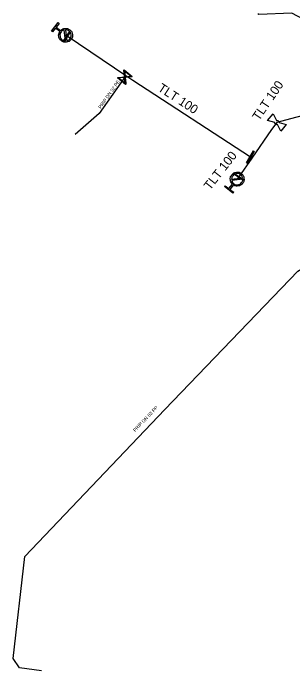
# Model space of a CAD drawing. Extents: x -643544 to -637295, y -1119190 to -1111715.
# Drawn here: x -642499.1 to -642458.3, y -1113951.4 to -1113855.6 of the extents above; entities that cross this region are included whole.
import ezdxf

# ---------------------------------------------------------------- set-up
doc = ezdxf.new("R2010")
doc.units = 0
for name, color, linetype in [('Default', 7, 'Continuous'), ('VP Hydrant', 7, 'Continuous'), ('VP Lomový bod', 7, 'Continuous'), ('VP Popis přípojky', 7, 'Continuous'), ('VP Přípojka', 7, 'Continuous'), ('VP Řad', 7, 'Continuous'), ('VP Řad - popis', 7, 'Continuous'), ('VP Šoupě', 7, 'Continuous')]:
    doc.layers.add(name, color=color, linetype=linetype)

msp = doc.modelspace()

# ---------------------------------------------------------------- linework, layer by layer
at = {"layer": 'Default'}
for points in [[(-642492.138, -1113858.184), (-642491.894, -1113857.919), (-642491.53, -1113857.876), (-642491.12, -1113857.827), (-642490.793, -1113858.083), (-642490.466, -1113858.338), (-642490.417, -1113858.749), (-642490.367, -1113859.16), (-642490.623, -1113859.487), (-642490.877, -1113859.812), (-642491.288, -1113859.863), (-642491.698, -1113859.914), (-642492.024, -1113859.659), (-642492.352, -1113859.403), (-642492.404, -1113858.993), (-642492.451, -1113858.629), (-642492.251, -1113858.329)], [(-642491.599, -1113858.078), (-642491.872, -1113858.139), (-642492.053, -1113858.37), (-642492.261, -1113858.636), (-642492.22, -1113858.969), (-642492.179, -1113859.302), (-642491.913, -1113859.51), (-642491.682, -1113859.691), (-642491.402, -1113859.684)], [(-642491.221, -1113859.662), (-642490.951, -1113859.598), (-642490.773, -1113859.371), (-642490.566, -1113859.106), (-642490.606, -1113858.772), (-642490.646, -1113858.438), (-642490.912, -1113858.23), (-642491.14, -1113858.052), (-642491.418, -1113858.056)], [(-642460.545, -1113871.868), (-642460.597, -1113871.877), (-642460.65, -1113871.868), (-642460.733, -1113871.854), (-642460.797, -1113871.803), (-642460.86, -1113871.751), (-642460.892, -1113871.67), (-642460.912, -1113871.621), (-642460.913, -1113871.568)], [(-642460.656, -1113871.251), (-642460.604, -1113871.242), (-642460.551, -1113871.25), (-642460.467, -1113871.266), (-642460.403, -1113871.317), (-642460.34, -1113871.369), (-642460.309, -1113871.447), (-642460.289, -1113871.498), (-642460.288, -1113871.551)], [(-642467.086, -1113880.528), (-642467.351, -1113880.284), (-642467.394, -1113879.92), (-642467.443, -1113879.51), (-642467.186, -1113879.183), (-642466.931, -1113878.856), (-642466.521, -1113878.807), (-642466.11, -1113878.757), (-642465.782, -1113879.013), (-642465.458, -1113879.267), (-642465.407, -1113879.678), (-642465.356, -1113880.088), (-642465.611, -1113880.414), (-642465.867, -1113880.742), (-642466.277, -1113880.794), (-642466.641, -1113880.841), (-642466.941, -1113880.641)], [(-642465.608, -1113879.611), (-642465.671, -1113879.341), (-642465.899, -1113879.163), (-642466.164, -1113878.956), (-642466.498, -1113878.996), (-642466.832, -1113879.036), (-642467.04, -1113879.302), (-642467.218, -1113879.53), (-642467.214, -1113879.808)], [(-642467.192, -1113879.989), (-642467.131, -1113880.262), (-642466.9, -1113880.443), (-642466.634, -1113880.651), (-642466.301, -1113880.61), (-642465.967, -1113880.569), (-642465.759, -1113880.303), (-642465.579, -1113880.072), (-642465.585, -1113879.792)]]:
    msp.add_open_spline(points, degree=3, dxfattribs=at)
at = {"layer": 'VP Hydrant'}
for points in [[(-642492.251, -1113858.329), (-642492.898, -1113857.824), (-642493.322, -1113858.367), (-642493.467, -1113858.254), (-642492.504, -1113857.023), (-642492.36, -1113857.136), (-642492.784, -1113857.679), (-642492.138, -1113858.184)], [(-642491.402, -1113859.684), (-642491.599, -1113858.078)], [(-642491.418, -1113858.056), (-642491.221, -1113859.662)], [(-642467.214, -1113879.808), (-642465.608, -1113879.611)], [(-642465.585, -1113879.792), (-642467.192, -1113879.989)], [(-642466.941, -1113880.641), (-642467.446, -1113881.288), (-642466.903, -1113881.712), (-642467.016, -1113881.857), (-642468.247, -1113880.894), (-642468.134, -1113880.75), (-642467.591, -1113881.174), (-642467.086, -1113880.528)]]:
    msp.add_lwpolyline(points, dxfattribs=at)
at = {"layer": 'VP Lomový bod'}
for points in [[(-642461.964, -1113871.257), (-642461.176, -1113870.287), (-642460.656, -1113871.251)], [(-642460.913, -1113871.568), (-642461.964, -1113871.257)], [(-642460.288, -1113871.551), (-642459.236, -1113871.863), (-642460.024, -1113872.833), (-642460.545, -1113871.868)]]:
    msp.add_lwpolyline(points, dxfattribs=at)
at = {"layer": 'VP Přípojka'}
for points in [[(-642450.87, -1113859.6), (-642451.1, -1113859.51), (-642458.41, -1113855.64), (-642463.23, -1113855.84), (-642463.41, -1113855.75)], [(-642482.63, -1113864.74), (-642482.77, -1113864.95), (-642486.51, -1113870.25), (-642490.03, -1113873.29)], [(-642494.94, -1113951.37), (-642498.13, -1113950.92), (-642499.05, -1113949.58), (-642497.33, -1113934.73), (-642476.94, -1113913.33), (-642457.54, -1113893.19), (-642453.65, -1113890.9), (-642448.78, -1113891.98), (-642444.1, -1113895.89), (-642443.13, -1113895.62), (-642436.151, -1113888.472), (-642434.43, -1113886.71), (-642434.316, -1113886.594)]]:
    msp.add_lwpolyline(points, dxfattribs=at)
at = {"layer": 'VP Řad'}
for points in [[(-642464.25, -1113876.73), (-642464.48, -1113876.6), (-642481.62, -1113865.42), (-642482.63, -1113864.74), (-642491.2, -1113859.01), (-642491.41, -1113858.87)], [(-642454.52, -1113868.74), (-642454.67, -1113868.67), (-642454.88, -1113868.8), (-642456.58, -1113870.49), (-642458.607, -1113871.01), (-642460.6, -1113871.56), (-642461.42, -1113872.57), (-642464.25, -1113876.73)], [(-642464.25, -1113876.73), (-642466.15, -1113879.48), (-642466.4, -1113879.8)]]:
    msp.add_lwpolyline(points, dxfattribs=at)
at = {"layer": 'VP Šoupě'}
for points in [[(-642491.656, -1113859.608), (-642490.822, -1113858.361), (-642490.744, -1113858.413), (-642491.578, -1113859.66), (-642491.656, -1113859.608)], [(-642482.672, -1113866.006), (-642483.826, -1113865.048), (-642483.784, -1113864.997), (-642483.656, -1113864.989), (-642482.819, -1113864.911), (-642482.91, -1113863.945), (-642482.868, -1113863.894), (-642481.714, -1113864.852), (-642481.756, -1113864.903), (-642482.724, -1113864.99), (-642482.645, -1113865.827), (-642482.63, -1113865.955), (-642482.672, -1113866.006)], [(-642482.81, -1113864.063), (-642482.732, -1113864.903), (-642481.894, -1113864.824), (-642482.81, -1113864.063)], [(-642482.734, -1113865.833), (-642482.811, -1113864.999), (-642483.645, -1113865.077), (-642482.734, -1113865.833)], [(-642465.026, -1113877.44), (-642464.042, -1113875.699), (-642463.934, -1113875.76), (-642464.918, -1113877.501), (-642465.026, -1113877.44)], [(-642466.747, -1113879.024), (-642465.5, -1113879.858), (-642465.553, -1113879.936), (-642466.8, -1113879.102), (-642466.747, -1113879.024)]]:
    msp.add_lwpolyline(points, dxfattribs=at)

# ---------------------------------------------------------------- texts
at = {"layer": 'VP Popis přípojky'}
for s, rotation, p in [('PRIP DN 32 PE', 54.7909, (-642486.271, -1113869.601)), ('PRIP DN 63 PP', 46.38449, (-642481.262, -1113916.636))]:
    msp.add_text(s, height=0.5, rotation=rotation, dxfattribs=at).set_placement(p)
at = {"layer": 'VP Řad - popis'}
for rotation, p in [(326.88458, (-642478.071, -1113866.851)), (55.773, (-642463.218, -1113871.395)), (51.98325, (-642470.348, -1113881.493))]:
    msp.add_text('TLT 100', height=1.3, rotation=rotation, dxfattribs=at).set_placement(p)

doc.saveas('drawing.dxf')
